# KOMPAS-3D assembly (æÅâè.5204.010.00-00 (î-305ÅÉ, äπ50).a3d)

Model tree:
1. Плоскость XY
2. Плоскость ZX
3. Плоскость ZY
4. Ось X
5. Ось Y
6. Ось Z
7. Начало координат  (labels: Операция без истории:1; ␣0; ␣1; ␣Ĳ␣2)

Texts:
  Линия-выноска #1
  Линия-выноска #2
  Линия-выноска #3
  Отклонения формы и база
  Марка координационной оси
  Марка/позиционное обозначение с линией-выноской
  Марка/позиционное обозначение на линии
  Марка/позиционное обозначение без линии-выноски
